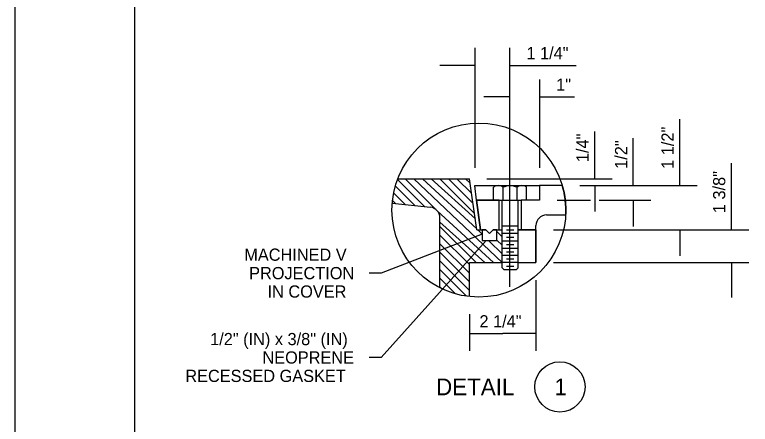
# Model space of a CAD drawing. Extents: x 99988 to 100172, y 99995 to 100047.
# Drawn here: x 99999.312 to 100003.533, y 100001.196 to 100003.543 of the extents above; entities that cross this region are included whole.
import ezdxf

# ---------------------------------------------------------------- set-up
doc = ezdxf.new("R2010")
doc.units = 0
for name, color, linetype in [('Level 1', 7, 'Continuous'), ('Level 15', 7, 'Continuous'), ('Level 2', 7, 'Continuous'), ('Level 20', 7, 'Continuous'), ('Level 3', 7, 'Continuous'), ('Level 9', 7, 'Continuous'), ('SH_GI_PlotLimits', 7, 'Continuous'), ('SH_GI_SheetBorder', 7, 'Continuous'), ('SH_RS_ConstructionNoteFlag', 7, 'Continuous'), ('SH_RS_DimensionLines', 7, 'Continuous')]:
    doc.layers.add(name, color=color, linetype=linetype)

msp = doc.modelspace()

# ---------------------------------------------------------------- linework, layer by layer
at = {"layer": 'Level 1'}
for p, q in [((100001.5109, 100002.6038), (100001.922, 100002.6038)), ((100001.9644, 100002.3112), (100001.9221, 100002.6038)), ((100001.9517, 100002.5652), (100002.3244, 100002.5652)), ((100001.963, 100002.4806), (100001.9517, 100002.5652)), ((100002.0602, 100002.4806), (100002.0602, 100002.5542)), ((100002.1149, 100002.4806), (100002.1149, 100002.5542)), ((100002.1951, 100002.4806), (100002.1951, 100002.5542)), ((100002.2498, 100002.4806), (100002.2498, 100002.5542)), ((100002.4543, 100002.5652), (100002.3244, 100002.5652)), ((100002.3244, 100002.5652), (100002.3244, 100002.4806)), ((100001.4788, 100002.4637), (100001.6983, 100002.4401)), ((100001.963, 100002.4806), (100002.0602, 100002.4806)), ((100001.9856, 100002.3112), (100001.963, 100002.4806)), ((100002.0602, 100002.4806), (100002.2185, 100002.4806)), ((100002.0915, 100002.3112), (100002.0915, 100002.4806)), ((100002.1085, 100002.0937), (100002.1085, 100002.4806)), ((100002.2015, 100002.0937), (100002.2015, 100002.4806)), ((100002.3244, 100002.4806), (100002.2185, 100002.4806)), ((100002.2185, 100002.4806), (100002.2185, 100002.3112)), ((100001.7527, 100001.9777), (100001.7527, 100002.3796)), ((100002.3641, 100002.3959), (100002.474, 100002.3959)), ((100002.1085, 100002.333), (100002.2015, 100002.333)), ((100002.3033, 100002.3112), (100002.3033, 100002.335)), ((100001.9644, 100002.3112), (100001.9949, 100002.3112)), ((100002.0783, 100002.3112), (100002.1085, 100002.3112)), ((100002.1085, 100002.2907), (100002.2015, 100002.2907)), ((100002.1338, 100002.3109), (100002.1762, 100002.3109)), ((100002.1992, 100002.3104), (100002.3032, 100002.3112)), ((100002.2185, 100002.3112), (100002.3033, 100002.3112)), ((100002.3033, 100002.3112), (100002.3033, 100002.1227)), ((100002.1085, 100002.2483), (100002.2015, 100002.2483)), ((100002.1338, 100002.2685), (100002.1762, 100002.2685)), ((100002.1085, 100002.206), (100002.2015, 100002.206)), ((100002.1338, 100002.2262), (100002.1762, 100002.2262)), ((100002.1085, 100002.1657), (100002.2015, 100002.1657)), ((100002.1338, 100002.1838), (100002.1762, 100002.1838)), ((100001.9221, 100001.9279), (100001.9221, 100002.1227)), ((100001.9221, 100002.1227), (100002.1085, 100002.1227)), ((100002.1085, 100002.1254), (100002.2015, 100002.1254)), ((100002.1338, 100002.1436), (100002.1762, 100002.1436)), ((100002.2015, 100002.1227), (100002.3033, 100002.1227)), ((100002.1191, 100002.0831), (100002.1085, 100002.0937)), ((100002.1191, 100002.0831), (100002.191, 100002.0831)), ((100002.1338, 100002.1033), (100002.1762, 100002.1033)), ((100002.2015, 100002.0937), (100002.191, 100002.0831))]:
    msp.add_line(p, q, dxfattribs=at)
msp.add_lwpolyline([(100002.0915, 100002.4806), (100002.0602, 100002.4806), (100001.963, 100002.4806), (100001.9856, 100002.3112), (100001.9949, 100002.3112), (100002.0158, 100002.3112), (100002.0366, 100002.2904), (100002.0574, 100002.3112), (100002.0783, 100002.3112), (100002.0915, 100002.3112), (100002.0915, 100002.4806)], dxfattribs=at)
for centre, radius, start, end in [((100002.0875, 100002.5256), 0.0397, 46.2447, 133.7553), ((100002.155, 100002.4647), 0.0981, 65.87, 114.13), ((100002.2225, 100002.5257), 0.0395, 46.1679, 133.8321), ((100001.9759, 100002.4238), 0.4988, 356.7912, 16.4729), ((100001.6918, 100002.3796), 0.0609, 0, 83.8871), ((100002.3641, 100002.335), 0.0609, 90, 180)]:
    msp.add_arc(centre, radius, start, end, dxfattribs=at)
at = {"layer": 'Level 15'}
for p, q in [((100001.9517, 100003.3534), (100001.9517, 100002.6652)), ((100002.1537, 100001.9831), (100002.1537, 100003.3534)), ((100002.3241, 100003.1724), (100002.3244, 100002.6652)), ((100002.022, 100002.6038), (100002.7404, 100002.6038)), ((100002.5543, 100002.5652), (100003.2286, 100002.5652)), ((100002.4244, 100002.4806), (100002.6154, 100002.4806)), ((100002.6654, 100002.4806), (100002.9618, 100002.4806)), ((100002.4033, 100002.3112), (100003.5247, 100002.3112)), ((100002.4033, 100002.1227), (100003.5247, 100002.1227)), ((100002.3033, 100002.0227), (100002.3033, 100001.6164)), ((100001.9221, 100001.8279), (100001.9221, 100001.6164)), ((100001.9221, 100001.7164), (100002.1127, 100001.7164)), ((100002.3033, 100001.7164), (100002.1127, 100001.7164))]:
    msp.add_line(p, q, dxfattribs=at)
for points in [[(100001.9949, 100002.2853), (100001.4154, 100002.0626), (100001.3454, 100002.0626)], [(100002.0176, 100002.2487), (100001.4154, 100001.5791), (100001.3454, 100001.5791)]]:
    msp.add_lwpolyline(points, dxfattribs=at)
at = {"layer": 'Level 2'}
msp.add_lwpolyline([(100001.9949, 100002.3112), (100001.9949, 100002.2487), (100002.0783, 100002.2487), (100002.0783, 100002.3112), (100002.0574, 100002.3112), (100002.0366, 100002.2904), (100002.0158, 100002.3112), (100001.9949, 100002.3112)], close=True, dxfattribs=at)
at = {"layer": 'Level 20'}
msp.add_circle((100002.4408, 100001.4105), 0.144, dxfattribs=at)
at = {"layer": 'Level 3'}
for p, q in [((100001.5091, 100002.5983), (100001.6635, 100002.4439)), ((100001.5531, 100002.6038), (100001.7309, 100002.426)), ((100001.6026, 100002.6038), (100002.1085, 100002.1229)), ((100001.6521, 100002.6038), (100001.9636, 100002.3172)), ((100001.7016, 100002.6038), (100001.956, 100002.3744)), ((100001.7511, 100002.6038), (100001.9484, 100002.4065)), ((100001.8006, 100002.6038), (100001.9407, 100002.4636)), ((100001.8501, 100002.6038), (100001.9331, 100002.5207)), ((100001.8996, 100002.6038), (100001.9255, 100002.5779)), ((100001.4967, 100002.5612), (100001.608, 100002.4499)), ((100001.4871, 100002.5213), (100001.5526, 100002.4558)), ((100001.4805, 100002.4784), (100001.4971, 100002.4618)), ((100001.7373, 100002.4196), (100002.0592, 100002.1227)), ((100001.7527, 100002.3547), (100002.0097, 100002.1227)), ((100001.7527, 100002.3302), (100001.9602, 100002.1227)), ((100001.7527, 100002.2807), (100001.9221, 100002.1113)), ((100001.7527, 100002.2312), (100001.9221, 100002.0618)), ((100001.7527, 100002.1817), (100001.9221, 100002.0123)), ((100001.7527, 100002.1322), (100001.9221, 100001.9628)), ((100001.7527, 100002.0827), (100001.9052, 100001.9302)), ((100001.7527, 100002.0332), (100001.8423, 100001.9436))]:
    msp.add_line(p, q, dxfattribs=at)
for points in [[(100002.4543, 100002.5652), (100002.3244, 100002.5652), (100002.3244, 100002.4806), (100002.2498, 100002.4806), (100002.2185, 100002.4806), (100002.2185, 100002.3112), (100002.2562, 100002.3112), (100002.3033, 100002.3112), (100002.3033, 100002.335)], [(100002.3641, 100002.3959), (100002.4739, 100002.3959)], [(100002.1999, 100002.1227), (100002.2015, 100002.1227), (100002.3032, 100002.1227), (100002.3033, 100002.1227), (100002.3033, 100002.3111), (100002.3032, 100002.3112), (100002.1993, 100002.3104)], [(100002.1993, 100002.3104), (100002.1999, 100002.1227)]]:
    msp.add_lwpolyline(points, dxfattribs=at)
for centre, radius, start, end in [((100001.9759, 100002.4238), 0.4988, 11.3501, 16.4729), ((100001.9767, 100002.424), 0.498, 356.7638, 11.3459), ((100002.3641, 100002.335), 0.0609, 90, 180)]:
    msp.add_arc(centre, radius, start, end, dxfattribs=at)
at = {"layer": 'Level 9'}
for p, q in [((100001.9697, 100002.3112), (100001.9926, 100002.2882)), ((100002.0804, 100002.2994), (100002.1085, 100002.2714)), ((100002.0342, 100002.2466), (100002.1085, 100002.1724)), ((100002.0791, 100002.2512), (100002.1085, 100002.2219)), ((100001.7527, 100001.9837), (100001.7637, 100001.9727))]:
    msp.add_line(p, q, dxfattribs=at)
msp.add_circle((100001.9759, 100002.4238), 0.4988, dxfattribs=at)
at = {"layer": 'SH_GI_PlotLimits'}
msp.add_lwpolyline([(99999.3125, 99999.9375), (100015.8125, 99999.9375), (100015.8125, 100010.4375), (99999.3125, 100010.4375)], close=True, dxfattribs=at)
at = {"layer": 'SH_GI_SheetBorder'}
msp.add_line((100000, 100010.375), (100000, 100000), dxfattribs=at)
at = {"layer": 'SH_RS_DimensionLines'}
for p, q in [((100001.9517, 100003.2534), (100001.7517, 100003.2534)), ((100002.1537, 100003.2534), (100002.5343, 100003.2534)), ((100002.1537, 100003.0724), (100002.0037, 100003.0724)), ((100002.3241, 100003.0724), (100002.5241, 100003.0724)), ((100003.1286, 100002.5652), (100003.1286, 100002.9458)), ((100002.6404, 100002.6038), (100002.6404, 100002.8738)), ((100002.8618, 100002.5652), (100002.8618, 100002.8352)), ((100003.4247, 100002.3112), (100003.4247, 100002.6918)), ((100002.6404, 100002.5652), (100002.6404, 100002.4152)), ((100002.8618, 100002.4806), (100002.8618, 100002.3306)), ((100003.1286, 100002.3112), (100003.1286, 100002.1612)), ((100003.4247, 100002.1227), (100003.4247, 100001.9227))]:
    msp.add_line(p, q, dxfattribs=at)

# ---------------------------------------------------------------- texts
at = {"layer": 'Level 20'}
for s, height, p in [('MACHINED V ', 0.07, (100000.6297, 100002.1332)), ('PROJECTION', 0.07, (100000.6574, 100002.0276)), ('IN COVER', 0.07, (100000.7633, 100001.922)), ('2 1/4"', 0.07, (100001.9792, 100001.7514)), ('1/2" (IN) x 3/8" (IN)', 0.07, (100000.4339, 100001.6496)), ('NEOPRENE', 0.07, (100000.734, 100001.5441)), ('RECESSED GASKET', 0.07, (100000.2914, 100001.4385)), ('DETAIL', 0.096, (100001.7301, 100001.3624)), ('1', 0.096, (100002.4096, 100001.3624))]:
    msp.add_text(s, height=height, dxfattribs=at).set_placement(p)
at = {"layer": 'SH_RS_ConstructionNoteFlag'}
for s, rotation, p in [('1 1/4"', 360, (100002.2487, 100003.2884)), ('1 1/2"', 90, (100003.0936, 100002.6602)), ('1/4"', 90, (100002.6054, 100002.6987)), ('1/2"', 90, (100002.8268, 100002.6602)), ('1 3/8"', 90, (100003.3897, 100002.4061))]:
    msp.add_text(s, height=0.07, rotation=rotation, dxfattribs=at).set_placement(p)
msp.add_text('1"', height=0.07, dxfattribs=at).set_placement((100002.4191, 100003.1074))

doc.saveas('drawing.dxf')
